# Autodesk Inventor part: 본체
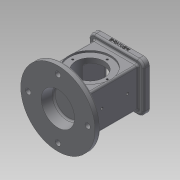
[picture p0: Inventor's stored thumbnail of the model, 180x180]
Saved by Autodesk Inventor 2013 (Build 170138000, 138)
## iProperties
Created: 2018-10
Part Number: 본체
Material: 일반
Document SubType Name: Modeling
Designer: Administrator
Density: 1 g/cm^3
Mass: 364.463 g
Surface Area: 745.252 cm^2
Volume: 364.463 cm^3
Author: Administrator
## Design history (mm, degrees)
sketch "스케치1"
  geometry: C1 r 62.5 at (0, 0); 1 further point
  constraints: 1 centre point, 1 coincident
  dimensions: "d0" = 125 diameter of C1
extrude "돌출1" new body sketch "스케치1" distance "d1" = 10; taper "d2" = 0 deg
sketch "스케치2"
  geometry: L1 (-37, -33)-(37, -33); L2 (37, -33)-(37, 33); L3 (37, 33)-(-37, 33); L4 (-37, 33)-(-37, -33); L5 (-37, -33)-(37, 33); L6 (37, -33)-(-37, 33); C1 r 62.5 at (0, 0) reference
  constraints: 12 end point, 2 midpoint, 2 parallel, 1 horizontal, 1 perpendicular
  dimensions: "d3" = 74 distance of L3.end L2.end; "d4" = 66 distance of L2.end L1.end
extrude "돌출2" join sketch "스케치2" distance "d5" = 88; taper "d6" = 0 deg
sketch "스케치3"
  geometry: L1 (-46, -41)-(46, -41); L2 (46, -41)-(46, 41); L3 (46, 41)-(-46, 41); L4 (-46, 41)-(-46, -41); L5 (-46, -41)-(46, 41); L6 (46, -41)-(-46, 41); 1 further point
  constraints: 12 end point, 2 midpoint, 2 parallel, 1 horizontal, 1 perpendicular
  dimensions: "d7" = 92 distance of L3.end L2.end; "d8" = 82 distance of L2.end L1.end
extrude "돌출3" join sketch "스케치3" distance "d9" = 10; taper "d10" = 0 deg
sketch "스케치4"
  geometry: L1 (26, -26)-(-26, -26); L2 (-26, -26)-(-26, 26); L3 (-26, 26)-(26, 26); L4 (26, 26)-(26, -26); L5 (26, -26)-(-26, 26); L6 (-26, -26)-(26, 26); 1 further point
  constraints: 12 end point, 2 midpoint, 2 parallel, 1 horizontal, 1 perpendicular
  dimensions: "d11" = 52 distance of L2.end L3.end; "d12" = 52 distance of L1.end L2.end
extrude "돌출4" cut sketch "스케치4" distance "d13" = 8; taper "d14" = 0 deg
sketch "스케치5"
  geometry: L1 (22, -22)-(-22, -22); L2 (-22, -22)-(-22, 22); L3 (-22, 22)-(22, 22); L4 (22, 22)-(22, -22); L5 (22, -22)-(-22, 22); L6 (-22, -22)-(22, 22); 1 further point
  constraints: 12 end point, 2 midpoint, 2 parallel, 1 horizontal, 1 perpendicular
  dimensions: "d15" = 44 distance of L2.end L3.end; "d16" = 44 distance of L1.end L2.end
extrude "돌출5" cut sketch "스케치5" distance "d17" = 74; taper "d18" = 0 deg
sketch "스케치6"
  geometry: C1 r 62.5 at (0, 0) reference; C2 r 28 at (0, 0)
  constraints: 1 centre point, 1 coincident
  dimensions: "d19" = 56 diameter of C2
extrude "돌출6" cut sketch "스케치6" distance "d20" = 18; taper "d21" = -10 deg
sketch "스케치7"
  geometry: C1 r 62.5 at (0, 0) reference; C2 r 4.5 at (-50, 0)
  constraints: 1 centre point, 1 horizontal alignment
  dimensions: "d22" = 9 diameter of C2; "d23" = 50 distance of C2.centre C1.centre
extrude "돌출7" cut sketch "스케치7" distance "d24" = 18; taper "d25" = 0 deg
fillet "모깎기1" dims "d29" = 3, "d30" = 10
fillet "모깎기2" dims "d31" = 3
sketch "스케치8"
  geometry: L1 (-28.5, -13)-(96.5, -13) reference; C1 r 35 at (34, 41); 1 further point
  constraints: 1 centre point, 1 vertical alignment
  dimensions: "d32" = 70 diameter of C1; "d33" = 54 distance from line of L1 C1.centre
extrude "돌출8" cut sketch "스케치8" distance "d34" = 3; taper "d35" = 0 deg
sketch "스케치9"
  geometry: C1 r 35 at (0, 0) reference; C2 r 24 at (0, 0); 1 further point
  constraints: 1 centre point, 1 coincident
  dimensions: "d36" = 48 diameter of C2
fillet "모깎기3" dims "d37" = 3
fillet "모깎기4" dims "d38" = 3
extrude "돌출9" cut sketch "스케치9" stored distance "d39" = 3; taper "d40" = 0 deg
sketch "스케치10"
  geometry: A1 r 10 centre (-36, -31) between (-46, -31) and (-36, -41) reference; A2 r 10 centre (36, -31) between (36, -41) and (46, -31) reference; A3 r 10 centre (36, 31) between (46, 31) and (36, 41) reference; A4 r 10 centre (-36, 31) between (-36, 41) and (-46, 31) reference; 1 further point
hole "구멍1" sketch "스케치10" at (-36, 31), (36, 31), (36, -31), (-36, -31) diameter "d41" = 3.242; stored, may be unused: countersink angle "d45" = 90 deg, drill point angle "d47" = 118 deg; dims "d42" = 4, "d43" = 4, "d44" = 2, "d46" = 6
sketch "스케치11"
  geometry: C1 r 24 at (0, 0) reference; 2 further points
  constraints: 1 vertical alignment
  dimensions: "d48" = 29 distance of point (0, 29) C1.centre
hole "구멍2" sketch "스케치11" at (0, 29) diameter "d49" = 3.242; stored, may be unused: countersink angle "d53" = 90 deg, drill point angle "d55" = 118 deg; dims "d50" = 4, "d51" = 4, "d52" = 2, "d54" = 6
sketch "스케치12"
  geometry: L1 (0, 0)-(72, 0) reference; L2 (17, -8)-(17, -39.337) reference; 3 further points
  constraints: 1 vertical alignment, 2 other
  dimensions: "d59" = 4 distance from line of L1 point (36, -4)
feature "엠보싱1" sketch "스케치12" dims "d60" = 0.5, "d61" = 0
sketch "스케치13"
  geometry: L1 (-92.5, -13)-(32.5, -13) reference; 3 further points
  constraints: 2 vertical alignment
  dimensions: "d62" = 37 distance from line of L1 point (-30, 24); "d63" = 43 distance of point (-30, 24) point (-30, 67)
hole "구멍3" sketch "스케치13" at (-30, 67), (-30, 24) diameter "d64" = 4.134; stored, may be unused: countersink angle "d68" = 90 deg, drill point angle "d70" = 118 deg; dims "d65" = 30, "d66" = 4, "d67" = 2, "d69" = 30
chamfer "모따기1" distance "d71" = 1; stored, may be unused: second distance "d72" = 2, angle "d73" = 45 deg
node "솔리드1"
pattern_circular "원형 패턴1" dims angle "d27" = 360 deg
mirror "대칭1"
pattern_circular "원형 패턴2" dims angle "d57" = 360 deg
mirror "대칭2"
